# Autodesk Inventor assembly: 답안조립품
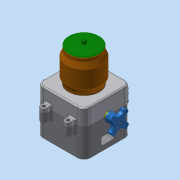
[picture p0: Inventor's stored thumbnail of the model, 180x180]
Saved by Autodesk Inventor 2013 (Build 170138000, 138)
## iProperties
Created: 2018-01
Part Number: 답안조립품
Document SubType Name: Assembly
Designer: dgall
Author: dgall
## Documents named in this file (9)
- C:\Users\dgall\Desktop\480107V1024\답안조립품.iam
- C:\Users\dgall\Desktop\480107V1024\본체.ipt
- C:\Users\dgall\Desktop\480107V1024\본체커버.ipt
- C:\Users\dgall\Desktop\480107V1024\용기.ipt
- C:\Users\dgall\Desktop\480107V1024\용기캡.ipt
- C:\Users\dgall\Desktop\480107V1024\핸들.ipt
- C:\Users\dgall\Desktop\480107V1024\핸들축.ipt
- C:\Users\dgall\Desktop\480107V1024\볼트 M3x12.ipt
- C:\Users\dgall\Desktop\480107V1024\볼트 M4x12.ipt
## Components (2 placed, 2 different names)
1. 핸들:1
2. 핸들축:1
